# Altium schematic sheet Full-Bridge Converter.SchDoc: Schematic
size A3; DocumentNumber: 1; SheetNumber: 1; SheetTotal: 2
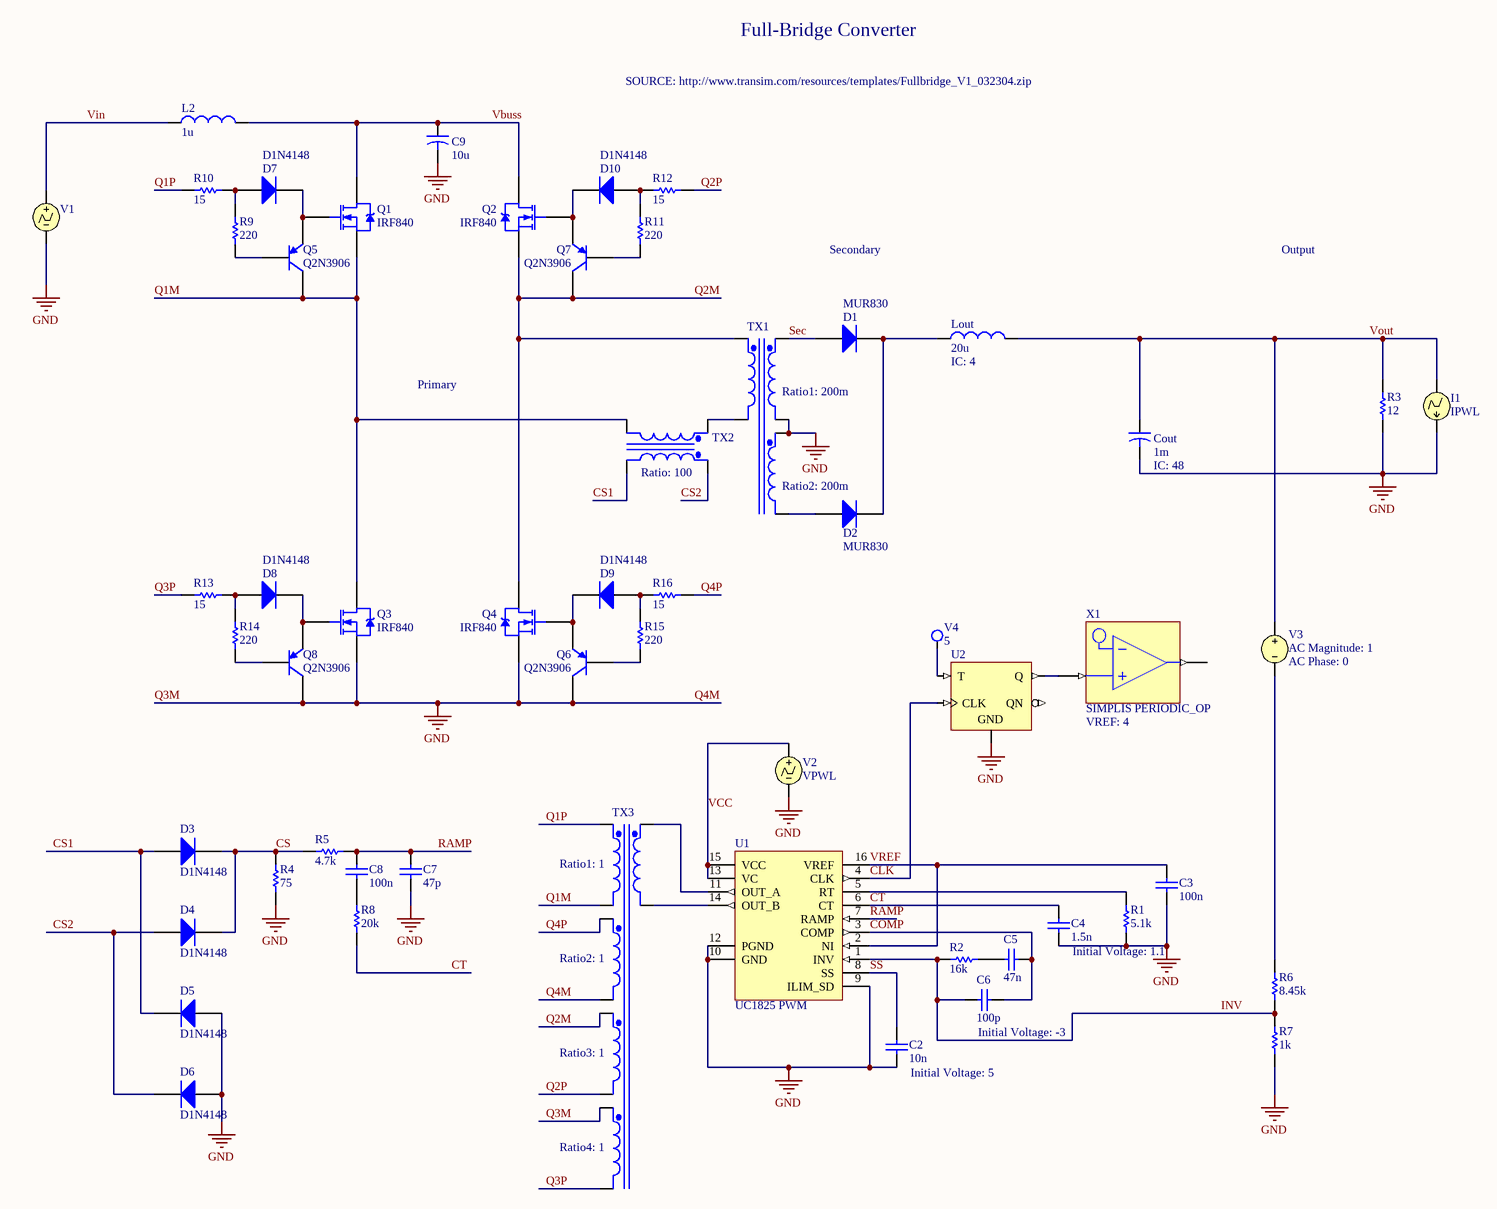
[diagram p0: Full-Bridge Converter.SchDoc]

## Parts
C2  value 10n  Initial Voltage: 5  [RAD-0.3]  (hidden comment: Cap)
C3  value 100n  [RAD-0.3]  (hidden comment: Cap)
C4  value 1.5n  Initial Voltage: 1.1  [RAD-0.3]  (hidden comment: Cap)
C5  value 47n  [RAD-0.3]  (hidden comment: Cap)
C6  value 100p  Initial Voltage: -3  [RAD-0.3]  (hidden comment: Cap)
C7  value 47p  [RAD-0.3]  (hidden comment: Cap)
C8  value 100n  [RAD-0.3]  (hidden comment: Cap)
C9  CC: 10u  [CAPR5-4X5]  (hidden comment: Cap Elec (L1-3))
Cout  IC: 48  CC: 1m  [CAPR5-4X5]  (hidden comment: Cap Elec (L1-3))
D1  MUR830  [SMC]
D2  MUR830  [SMC]
D3  D1N4148  [DO-35]
D4  D1N4148  [DO-35]
D5  D1N4148  [DO-35]
D6  D1N4148  [DO-35]
D7  D1N4148  [DO-35]
D8  D1N4148  [DO-35]
D9  D1N4148  [DO-35]
D10  D1N4148  [DO-35]
I1  IPWL  [HDR1X2H]
L2  value 1u  [0402-A]  (hidden comment: Lossy Inductor)
Lout  value 20u  IC: 4  [0402-A]  (hidden comment: Lossy Inductor)
Q1  IRF840  [TO-220AB]
Q2  IRF840  [TO-220AB]
Q3  IRF840  [TO-220AB]
Q4  IRF840  [TO-220AB]
Q5  Q2N3906  [TO-92A]
Q6  Q2N3906  [TO-92A]
Q7  Q2N3906  [TO-92A]
Q8  Q2N3906  [TO-92A]
R1  value 5.1k  [AXIAL-0.3]  (hidden comment: Res1)
R2  value 16k  [AXIAL-0.3]  (hidden comment: Res1)
R3  value 12  [AXIAL-0.3]  (hidden comment: Res1)
R4  value 75  [AXIAL-0.3]  (hidden comment: Res1)
R5  value 4.7k  [AXIAL-0.3]  (hidden comment: Res1)
R6  value 8.45k  [AXIAL-0.3]  (hidden comment: Res1)
R7  value 1k  [AXIAL-0.3]  (hidden comment: Res1)
R8  value 20k  [AXIAL-0.3]  (hidden comment: Res1)
R9  value 220  [AXIAL-0.3]  (hidden comment: Res1)
R10  value 15  [AXIAL-0.3]  (hidden comment: Res1)
R11  value 220  [AXIAL-0.3]  (hidden comment: Res1)
R12  value 15  [AXIAL-0.3]  (hidden comment: Res1)
R13  value 15  [AXIAL-0.3]  (hidden comment: Res1)
R14  value 220  [AXIAL-0.3]  (hidden comment: Res1)
R15  value 220  [AXIAL-0.3]  (hidden comment: Res1)
R16  value 15  [AXIAL-0.3]  (hidden comment: Res1)
TX1  Ratio1: 200m  [TRF_6]  (hidden comment: Trans3 Simpl)
TX2  Ratio: 100  [TRF_4]  (hidden comment: Trans Simpl)
TX3  Ratio1: 1  [TRF_10]  (hidden comment: Trans5 Simpl)
U1  UC1825 PWM
U2  SIMPLIS CLK_TFF  (value not drawn)
V1  VPWL  [HDR1X2H]  (value not drawn)
V2  VPWL  [HDR1X2H]
V3  AC Magnitude: 1  AC Phase: 0  (hidden comment: VSRC)
V4  value 5  (hidden comment: VSRC2)
X1  SIMPLIS PERIODIC_OP  VREF: 4

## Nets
Q3M: C2.2 C3.2 C4.2 C7.2 C9.2 Cout.2 D5.1(A) D6.1(A) I1.2 Q3.3(S) Q4.3(S) Q6.3(C) Q8.3(C) R1.2 R3.2 R4.2 R7.2 TX1.4(Sec1-) TX1.5(Sec2+) TX3.6(Sec2-) TX3.9(Sec4+) U1.9(ILIM_SD) U1.10(GND) U1.12(PGND) U2.100(GND) V1.2 V2.2  [also labelled GND, Q4M]
CLK: U1.4(CLK) U2.191(CLK)
COMP: C5.1 C6.1 U1.3(COMP)
CS: D3.2(K) D4.2(K) R4.1 R5.1
CS1: D3.1(A) D5.2(K) TX2.4(Sec-)
CS2: D4.1(A) D6.2(K) TX2.3(Sec+)
CT: C4.1 R8.2 U1.6(CT)
INV: C6.2 R2.2 R6.2 R7.1 U1.1(INV)
Q1M: Q1.3(S) Q3.2(D) Q5.3(C) TX2.2(Pri-) TX3.4(Sec1-)
Q1P: R10.1 TX3.3(Sec1+)
Q2M: Q2.3(S) Q4.2(D) Q7.3(C) TX1.1(Pri+) TX3.7(Sec3+)
Q2P: R12.2 TX3.8(Sec3-)
Q3P: R13.1 TX3.10(Sec4-)
Q4P: R16.2 TX3.5(Sec2+)
RAMP: C7.1 C8.1 R5.2 U1.7(RAMP)
Sec: D1.1(A) TX1.3(Sec1+)
SS: C2.1 U1.8(SS)
Vbuss: C9.1 L2.2 Q1.2(D) Q2.2(D)
VCC: U1.13(VC) U1.15(VCC) V2.1
Vin: L2.1 V1.1
Vout: Cout.1 I1.1 Lout.2 R3.1 V3.1
VREF: C3.1 U1.2(NI) U1.16(VREF)
NetC5_2: C5.2 R2.1
NetC8_2: C8.2 R8.1
NetD1_2: D1.2(K) D2.2(K) Lout.1
NetD2_1: D2.1(A) TX1.6(Sec2-)
NetD7_1: D7.1(A) R9.1 R10.2
NetD7_2: D7.2(K) Q1.1(G) Q5.1(E)
NetD8_1: D8.1(A) R13.2 R14.1
NetD8_2: D8.2(K) Q3.1(G) Q8.1(E)
NetD9_1: D9.1(A) R15.1 R16.1
NetD9_2: D9.2(K) Q4.1(G) Q6.1(E)
NetD10_1: D10.1(A) R11.1 R12.1
NetD10_2: D10.2(K) Q2.1(G) Q7.1(E)
NetQ5_2: Q5.2(B) R9.2
NetQ6_2: Q6.2(B) R15.2
NetQ7_2: Q7.2(B) R11.2
NetQ8_2: Q8.2(B) R14.2
NetR1_1: R1.1 U1.5(RT)
NetR6_1: R6.1 V3.2
NetTX1_2: TX1.2(Pri-) TX2.1(Pri+)
NetTX3_1: TX3.1(Pri+) U1.11(OUT_A)
NetTX3_2: TX3.2(Pri-) U1.14(OUT_B)
NetU2_101: U2.101(T) V4.1
NetU2_201: U2.201(Q) X1.1(IN)

Not connected (* = marked no-connect by the designer): U2 202(QN); X1 3(OUT)

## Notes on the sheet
- Full-Bridge Converter
- SOURCE: http://www.transim.com/resources/templates/Fullbridge_V1_032304.zip
- Secondary
- Output
- Primary

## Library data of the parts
C2-C8 = Cap: Capacitor
C9 Cout = Cap Elec (L1-3): Electrolytic Capacitor (Levels 1-3); LEVEL: 1; RSH_CC: 1Meg
D1 D2 = MUR830: General Purpose Fast Rectifier
D3-D10 = D1N4148: High Conductance Fast Diode
I1 = IPWL: Piecewise Linear Current Source; Sim Note: To add model file containing time-current pairs of values, enter model location under "General Tab" in "Full Path" box.; Time-Value Pairs: 20u 0 20u 0 30u 10
L2 = Inductor (Lossy): Code_IEC: 1005; RSERIES: 100m; RSHUNT: 1Meg
Lout = Inductor (Lossy): Code_IEC: 1005; USEIC: 1; RSERIES: 10m; RSHUNT: 1Meg
Q1-Q4 = IRF840: HEXFET N-Channel Power MOSFET; Note: Pin 2 is electrically connected to pin 4.
Q5-Q8 = Q2N3906: PNP General Purpose Amplifier
R1-R16 = Res1: Resistor
TX1 = Trans3 Simpl: Three-winding Transformer (Simplified Model); Sim Note: Enter the turns ratios, Core loss resistance, Magnetising Reactance, Leakage Reactances and Resistances referred to the primary side into the parameter fields.; L1: 10m
TX2 = Trans Simpl: Transformer (Simplified Model)
TX3 = Trans5 Simpl: Five-winding Transformer (Simplified Model); L1: 1m
U1 = UC1825: High-Speed PWM Controller
U2 = SIMPLIS CLK_TFF: Toggle Flip-Flop; SubClass: T; ClockTrigger: Rising; Enable: High; Reset: Asynchronous
V1 = VPWL: Piecewise Linear Voltage Source; Note: PCB Footprint - Not required; Sim Note: To add model file containing time-current pairs of values, enter model location under "General Tab" in "Full Path" box.; Time-Value Pairs: 0 400 0 400 10u 400
V2 = VPWL: Piecewise Linear Voltage Source; Note: PCB Footprint - Not required; Sim Note: To add model file containing time-current pairs of values, enter model location under "General Tab" in "Full Path" box.; Time-Value Pairs: 1p 12 1p 12 1p 12
V3 = VSRC: Voltage Source; Note: PCB Footprint - Not required; Value: 0
V4 = VSRC2: Voltage Source; Note: PCB Footprint - Not required
X1 = SIMPLIS PERIODIC_OP: Periodic Operating Point Analysis Trigger; XilinxEquivalent: XNOR2; FunctionalClass: Logic Primitive; SubClass: XNOR; PortSize: 2; PortStyle: Single Pin Version; ArchiveName: GENERIC; VHDLIB_SIM: GENERIC_LIB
